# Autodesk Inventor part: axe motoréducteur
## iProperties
Shininess: 64.0
Length Units: 11269
Angle Units: 11279
Time Units: 11290
Mass Units: 11283
Length Display Precision: 3
Angle Display Precision: 2
Compacted: True
Part Number: axe motoréducteur
Document SubType Name: Modeling
Created: 2005-02
Material: Par défaut
Designer: LEGERET Philippe
Density: 0.0
Volumn: 0.0
Area: 0.0
PropertySet Name: Model Information
Control State: 0
Master: False
Checked Out: False
Author: LEGERET Philippe
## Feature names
1. Extrusion1
2. Chanfrein1 [Chamfer]
3. Extrusion2
4. Extrusion3
